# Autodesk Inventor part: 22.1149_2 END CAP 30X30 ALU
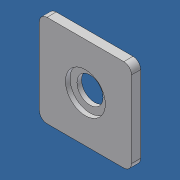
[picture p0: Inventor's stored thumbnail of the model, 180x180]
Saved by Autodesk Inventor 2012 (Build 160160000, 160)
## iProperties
Created: 2014-04
Part Number: 22.1149_2 END CAP 30X30 ALU
Material: Aluminum-6061
Document SubType Name: Modeling
Designer: Admin
Density: 2.71 g/cm^3
Mass: 6.50316 g
Surface Area: 21.2422 cm^2
Volume: 2.39969 cm^3
Author: Admin
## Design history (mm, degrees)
node "11"
node "Base1"
body "Solid1"
